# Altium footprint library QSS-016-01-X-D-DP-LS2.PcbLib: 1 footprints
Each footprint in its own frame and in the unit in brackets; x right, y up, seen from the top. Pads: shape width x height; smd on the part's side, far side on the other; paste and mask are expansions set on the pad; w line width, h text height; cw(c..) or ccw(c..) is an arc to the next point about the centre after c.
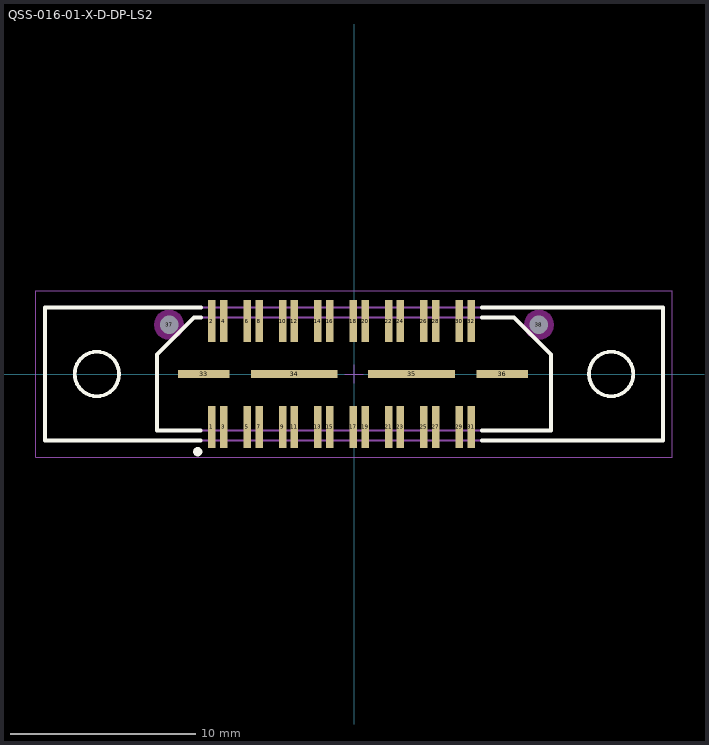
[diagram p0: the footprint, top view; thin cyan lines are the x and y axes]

## QSS-016-01-X-D-DP-LS2 [mm] "0.635mm pitch, 16 pin, high speed socket assembly; differential pair array"
height 3.43
pads (38):
  rect 0.4x2.25 smd mask+0: 1(-7.68,-2.865) 2(-7.68,2.865) 3(-7.04,-2.865) 4(-7.04,2.865) 5(-5.77,-2.865) 6(-5.77,2.865) 7(-5.13,-2.865) 8(-5.13,2.865) 9(-3.86,-2.865) 10(-3.86,2.865) 11(-3.22,-2.865) 12(-3.22,2.865) 13(-1.95,-2.865) 14(-1.95,2.865) 15(-1.31,-2.865) 16(-1.31,2.865) 17(-0.04,-2.865) 18(-0.04,2.865) 19(0.6,-2.865) 20(0.6,2.865) 21(1.87,-2.865) 22(1.87,2.865) 23(2.51,-2.865) 24(2.51,2.865) 25(3.78,-2.865) 26(3.78,2.865) 27(4.42,-2.865) 28(4.42,2.865) 29(5.69,-2.865) 30(5.69,2.865) 31(6.33,-2.865) 32(6.33,2.865)
  rect 2.8x0.45 smd mask+0: 33(-8.12,0) 36(8.01,0)
  rect 4.7x0.45 smd mask+0: 34(-3.23,0) 35(3.12,0)
  round 0.5 hole 1 unplated mask+0: 37(-10,2.655) 38(10,2.655)
Top Overlay:
  circle w0.2: c-13.9,0 r1.2
  circle w0.2: c13.9,0 r1.2
  circle w0.25: c-8.45,-4.2 r0.125
  lines w0.2: -8.3,-3.6 -16.7,-3.6 -16.7,3.6 -8.25,3.6 ; -8.3,-3.05 -10.65,-3.05 -10.65,1.05 -8.65,3.05 -8.25,3.05 ; 6.9,-3.6 16.7,-3.6 16.7,3.6 6.9,3.6 ; 6.9,-3.05 10.65,-3.05 10.65,1.05 8.65,3.05 6.9,3.05
Keep-Out Layer:
  pour cut-out: -9.193,2.655 -9.221,2.864 -9.301,3.058 -9.429,3.226 -9.597,3.354 -9.791,3.434 -10,3.462 -10.209,3.434 -10.403,3.354 -10.571,3.226 -10.699,3.058 -10.779,2.864 -10.807,2.655 -10.779,2.446 -10.699,2.252 -10.571,2.084 -10.403,1.956 -10.209,1.876 -10,1.848 -9.791,1.876 -9.597,1.956 -9.429,2.084 -9.301,2.252 -9.221,2.446
  pour cut-out: 10.807,2.655 10.779,2.864 10.699,3.058 10.571,3.226 10.403,3.354 10.209,3.434 10,3.462 9.791,3.434 9.597,3.354 9.429,3.226 9.301,3.058 9.221,2.864 9.193,2.655 9.221,2.446 9.301,2.252 9.429,2.084 9.597,1.956 9.791,1.876 10,1.848 10.209,1.876 10.403,1.956 10.571,2.084 10.699,2.252 10.779,2.446
Mechanical 12:
  lines w0.001: -16.7,-3.6 16.7,-3.6 16.7,3.6 -16.7,3.6 -16.7,-3.6
Mechanical 13:
  circle w0.1: c13.9,0 r1.2
  circle w0.1: c-13.9,0 r1.2
  lines w0.1: -16.7,-3.6 16.7,-3.6 16.7,3.6 -16.7,3.6 -16.7,-3.6 ; -10.65,-3.05 10.65,-3.05 10.65,1.057 8.657,3.05 -8.65,3.05 -10.65,1.05 -10.65,-3.05
  text ".Designator" at 0,0 h1.52
Mechanical 15:
  lines w0.05: -0.5,0 0.5,0 ; 0,-0.5 0,0.5 ; -17.2,-4.5 17.2,-4.5 17.2,4.5 -17.2,4.5 -17.2,-4.5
